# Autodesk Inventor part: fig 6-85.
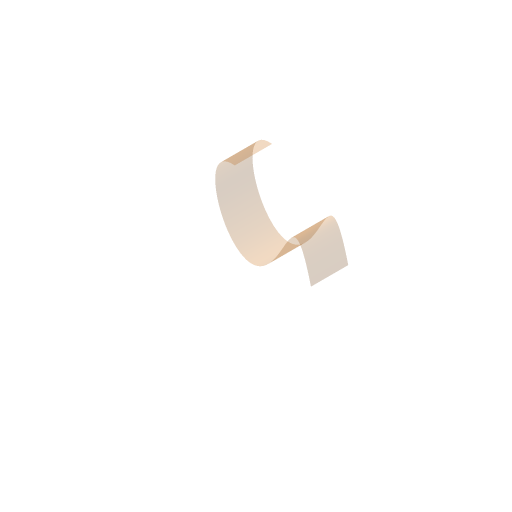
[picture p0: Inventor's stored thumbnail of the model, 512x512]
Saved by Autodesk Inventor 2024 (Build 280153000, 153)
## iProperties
Shininess: 64.0
Length Units: 11269
Angle Units: 11279
Time Units: 11290
Mass Units: 11283
Length Display Precision: 3
Angle Display Precision: 2
Compacted: True
Part Number: fig 6-85.
Document SubType Name: Modeling
Created: 2002-12
Designer: deepak
Density: 1 g/cm^3
Material: Generic
Appearance: Default
Density: 0.0
Volumn: 0.0
Area: 0.0
PropertySet Name: Model Information
Control State: 0
Master: False
Checked Out: False
Author: deepak
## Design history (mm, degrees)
sketch "Sketch1"
  geometry: 5 further points
  constraints: 5 other
extrude_surface "ExtrusionSrf1" sketch "Sketch1" dims "d0" = 20, "d1" = 0
body "Srf1"
